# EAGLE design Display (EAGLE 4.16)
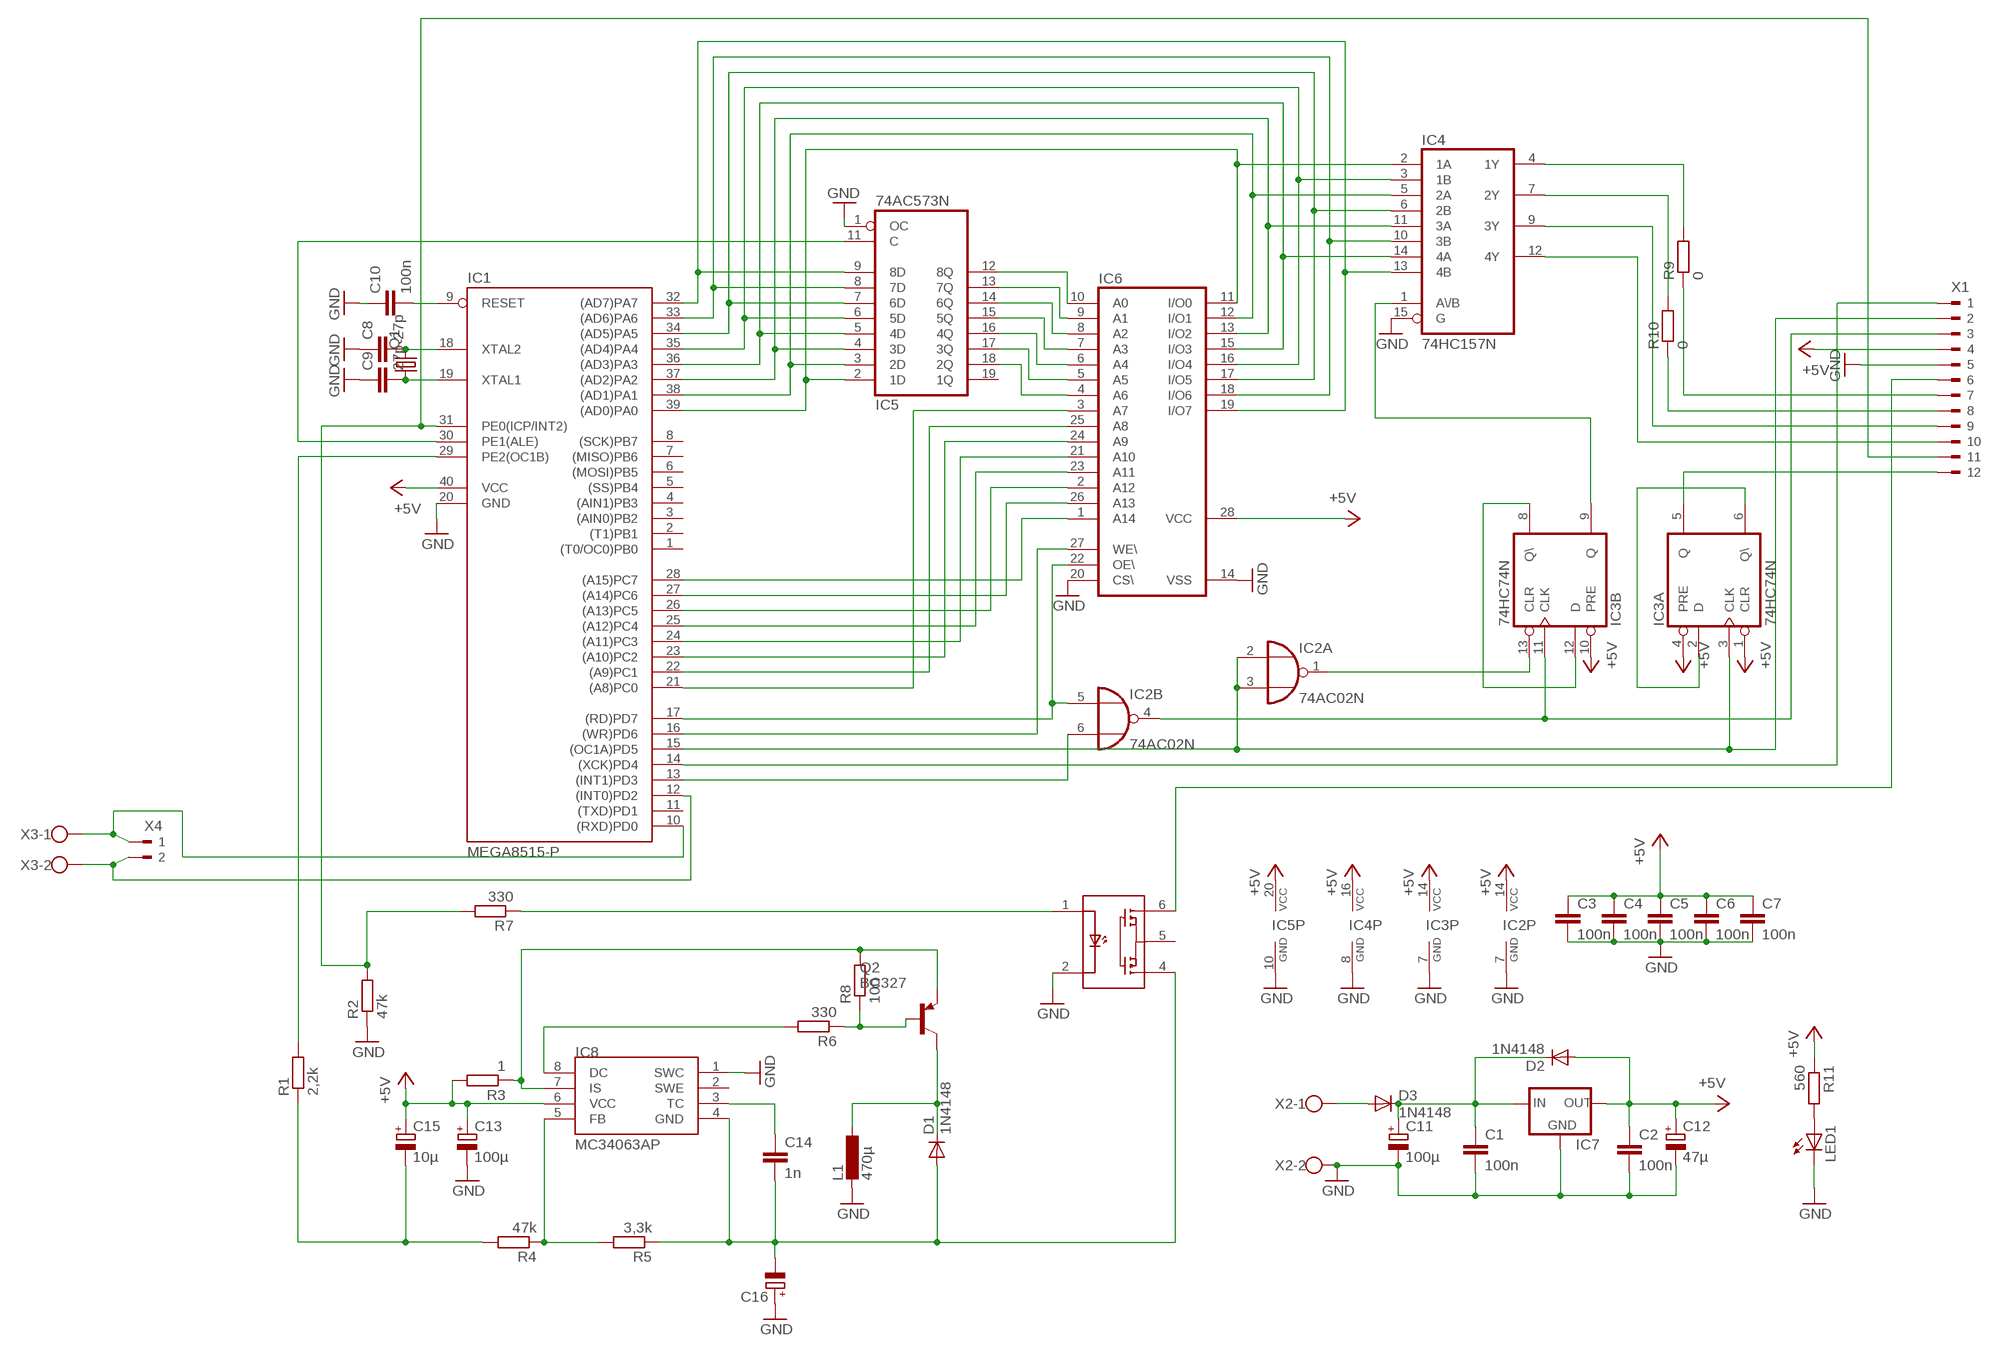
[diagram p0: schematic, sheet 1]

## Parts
C1  100n  C-EUC1206  [C1206]
C2  100n  C-EUC1206  [C1206]
C3  100n  C-EUC1206  [C1206]
C4  100n  C-EUC1206  [C1206]
C5  100n  C-EUC1206  [C1206]
C6  100n  C-EUC1206  [C1206]
C7  100n  C-EUC1206  [C1206]
C8  27p  C-EUC1206  [C1206]
C9  27p  C-EUC1206  [C1206]
C10  100n  C-EUC1206  [C1206]
C11  100µ  CPOL-EUE5-5  [E5-5]
C12  47µ  CPOL-EUE5-5  [E5-5]
C13  100µ  CPOL-EUE5-5  [E5-5]
C14  1n  C-EUC1206  [C1206]
C15  10µ  CPOL-EUE5-5  [E5-5]
C16  CPOL-EUE5-5  [E5-5]
D1  1N4148  [DO35-10]
D2  1N4148  [DO35-10]
D3  1N4148  [DO35-10]
IC1  MEGA8515-P  [DIL40]
IC2  74AC02N  [DIL14]
IC3  74HC74N  [DIL14]
IC4  74HC157N  [DIL16]
IC5  74AC573N  [DIL20]
IC6  62256P  [DIL28-6]
IC7  78XXS  [78XXS]
IC8  MC34063AP  [DIL08]
L1  470µ  L-EU0204/7  [0204/7]
LED1  LEDCHIPLED_1206  [CHIPLED_1206]
Q1  CRYSTALHC49U-V  [HC49U-V]
Q2  BC327  [TO92]
R1  2,2k  R-EU_M1206  [M1206]
R2  47k  R-EU_M1206  [M1206]
R3  1  R-EU_M1206  [M1206]
R4  47k  R-EU_M1206  [M1206]
R5  3,3k  R-EU_M1206  [M1206]
R6  330  R-EU_M1206  [M1206]
R7  330  R-EU_M1206  [M1206]
R8  100  R-EU_M1206  [M1206]
R9  0  R-EU_0207/10  [0207/10]
R10  0  R-EU_0207/10  [0207/10]
R11  560  R-EU_M1206  [M1206]
U$1  AQV254  [AQV257]
X1  180G-12  [180G-12]
X2  W237-102  [W237-102]
X3  W237-102  [W237-102]
X4  180-2  [180-2]

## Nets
+5V: C2.1 C3.1 C4.1 C5.1 C6.1 C7.1 C12.+ C13.+ C15.+ D2.A IC1.40(VCC) IC2.14(P:VCC) IC3.1(A:CLR) IC3.4(A:PRE) IC3.10(B:PRE) IC3.14(P:VCC) IC4.16(VCC) IC5.20(VCC) IC6.28(VCC) IC7.OUT IC8.6(VCC) R3.2 R11.1 X1.4
GND: C1.2 C2.2 C3.2 C4.2 C5.2 C6.2 C7.2 C8.1 C9.1 C10.1 C11.- C12.- C13.- C16.+ IC1.20(GND) IC2.7(P:GND) IC3.7(P:GND) IC4.8(GND) IC4.15(G) IC5.1(OC) IC5.10(GND) IC6.14(VSS) IC6.20(CS\) IC7.GND IC8.1(SWC) L1.2 LED1.C R2.1 U$1.2 X1.5 X2.2
N$1: IC1.39((AD0)PA0) IC4.2(1A) IC5.2(1D) IC6.11(I/O0)
N$2: IC1.38((AD1)PA1) IC4.5(2A) IC5.3(2D) IC6.12(I/O1)
N$3: IC1.37((AD2)PA2) IC4.11(3A) IC5.4(3D) IC6.13(I/O2)
N$4: IC1.36((AD3)PA3) IC4.14(4A) IC5.5(4D) IC6.15(I/O3)
N$5: IC1.35((AD4)PA4) IC4.3(1B) IC5.6(5D) IC6.16(I/O4)
N$6: IC1.34((AD5)PA5) IC4.6(2B) IC5.7(6D) IC6.17(I/O5)
N$7: IC1.33((AD6)PA6) IC4.10(3B) IC5.8(7D) IC6.18(I/O6)
N$8: IC1.32((AD7)PA7) IC4.13(4B) IC5.9(8D) IC6.19(I/O7)
N$9: IC5.12(8Q) IC6.10(A0)
N$10: IC5.13(7Q) IC6.9(A1)
N$11: IC5.14(6Q) IC6.8(A2)
N$12: IC5.15(5Q) IC6.7(A3)
N$13: IC5.16(4Q) IC6.6(A4)
N$14: IC5.17(3Q) IC6.5(A5)
N$15: IC5.18(2Q) IC6.4(A6)
N$16: IC1.21((A8)PC0) IC6.3(A7)
N$17: IC1.22((A9)PC1) IC6.25(A8)
N$18: IC1.23((A10)PC2) IC6.24(A9)
N$19: IC1.24((A11)PC3) IC6.21(A10)
N$20: IC1.25((A12)PC4) IC6.23(A11)
N$21: IC1.26((A13)PC5) IC6.2(A12)
N$22: IC1.27((A14)PC6) IC6.26(A13)
N$23: IC1.28((A15)PC7) IC6.1(A14)
N$24: IC1.16((WR)PD6) IC6.27(WE\)
N$25: IC1.17((RD)PD7) IC2.5(B:I0) IC6.22(OE\)
N$26: IC3.8(B:Q\) IC3.12(B:D)
N$27: IC3.9(B:Q) IC4.1(A\/B)
N$28: IC3.2(A:D) IC3.6(A:Q\)
N$29: IC2.1(A:O) IC3.13(B:CLR)
N$30: IC1.10((RXD)PD0) X3.1 X4.1
N$31: IC1.13((INT1)PD3) IC2.6(B:I1)
N$32: C8.2 IC1.18(XTAL2) Q1.2
N$33: C9.2 IC1.19(XTAL1) Q1.1
N$34: C10.2 IC1.9(RESET)
N$35: IC1.31(PE0(ICP/INT2)) R2.2 R7.2 X1.11
N$36: IC1.15((OC1A)PD5) IC2.2(A:I0) IC2.3(A:I1) IC3.3(A:CLK) X1.2
N$37: IC1.30(PE1(ALE)) IC5.11(C)
N$38: IC3.5(A:Q) X1.12
N$39: IC2.4(B:O) IC3.11(B:CLK) X1.3
N$40: R9.1 X1.7
N$41: R10.1 X1.8
N$42: IC4.9(3Y) X1.9
N$43: IC4.12(4Y) X1.10
N$44: IC1.12((INT0)PD2) X3.2 X4.2
N$45: C14.1 IC8.3(TC)
N$46: C14.2 C16.- D1.A IC8.4(GND) R5.1 U$1.4
N$47: C1.1 C11.+ D2.C D3.C IC7.IN
N$48: IC8.5(FB) R4.1 R5.2
N$49: R7.1 U$1.1
N$50: LED1.A R11.2
N$51: C15.- R1.1 R4.2
N$52: IC1.29(PE2(OC1B)) R1.2
N$53: IC8.8(DC) R6.2
N$54: Q2.2(B) R6.1 R8.1
N$55: IC8.7(IS) Q2.1(E) R3.1 R8.2
N$56: D1.C L1.1 Q2.3(C)
N$57: U$1.6 X1.6
N$58: IC4.4(1Y) R9.2
N$59: IC4.7(2Y) R10.2
N$60: D3.A X2.1
N$61: IC1.14((XCK)PD4) X1.1
Unconnected: IC1.1((T0/OC0)PB0) IC1.2((T1)PB1) IC1.3((AIN0)PB2) IC1.4((AIN1)PB3) IC1.5((SS)PB4) IC1.6((MOSI)PB5) IC1.7((MISO)PB6) IC1.8((SCK)PB7) IC1.11((TXD)PD1) IC2.8(C:I0) IC2.9(C:I1) IC2.10(C:O) IC2.11(D:I0) IC2.12(D:I1) IC2.13(D:O) IC5.19(1Q) IC8.2(SWE) U$1.5

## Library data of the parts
C1-C10 C14 = rcl:C-EU: CAPACITOR, European symbol
C11-C13 C15 C16 = rcl:CPOL-EU: POLARIZED CAPACITOR, European symbol
D1-D3 = diode:1N4148: DIODE
IC1 = atmel:MEGA8515-P: MICROCONTROLLER 8 Kbytes FLASH 512 bytes SRAM 512 bytes EEPROM USART 8-channel 10 bit ADC Source: avr.lbr
IC2 = 74xx-eu:74*02: Quad 2-input NOR gate
IC3 = 74xx-eu:74*74: Dual D type positive edge triggered FLIP FLOP, preset and clear
IC4 = 74xx-eu:74*157: Quadruple 2-line to 1-line data SELECTOR/MULTIPLEXER
IC5 = 74xx-eu:74*573: 8-bit D latch BUS DRIVER
IC6 = memory-hitachi:62256P: MEMORY
IC7 = v-reg:78XXS: VOLTAGE REGULATOR
IC8 = mc34063:MC34063
L1 = rcl:L-EU: INDUCTOR, European symbol
LED1 = led:LED: LED
Q1 = crystal:CRYSTAL: CRYSTAL
Q2 = transistor-pnp:BC327: PNP Transistor
R1-R11 = rcl:R-EU_: RESISTOR, European symbol
U$1 = Relais-Opto:AQV254
X1 = con-weidmueller-sl35:180G-12: WEIDMUELLER CLAMP CONNECTOR
X2 X3 = con-wago-500:W237-102: WAGO SCREW CLAMP
X4 = con-weidmueller-sl35:180-2: WEIDMUELLER CLAMP CONNECTOR

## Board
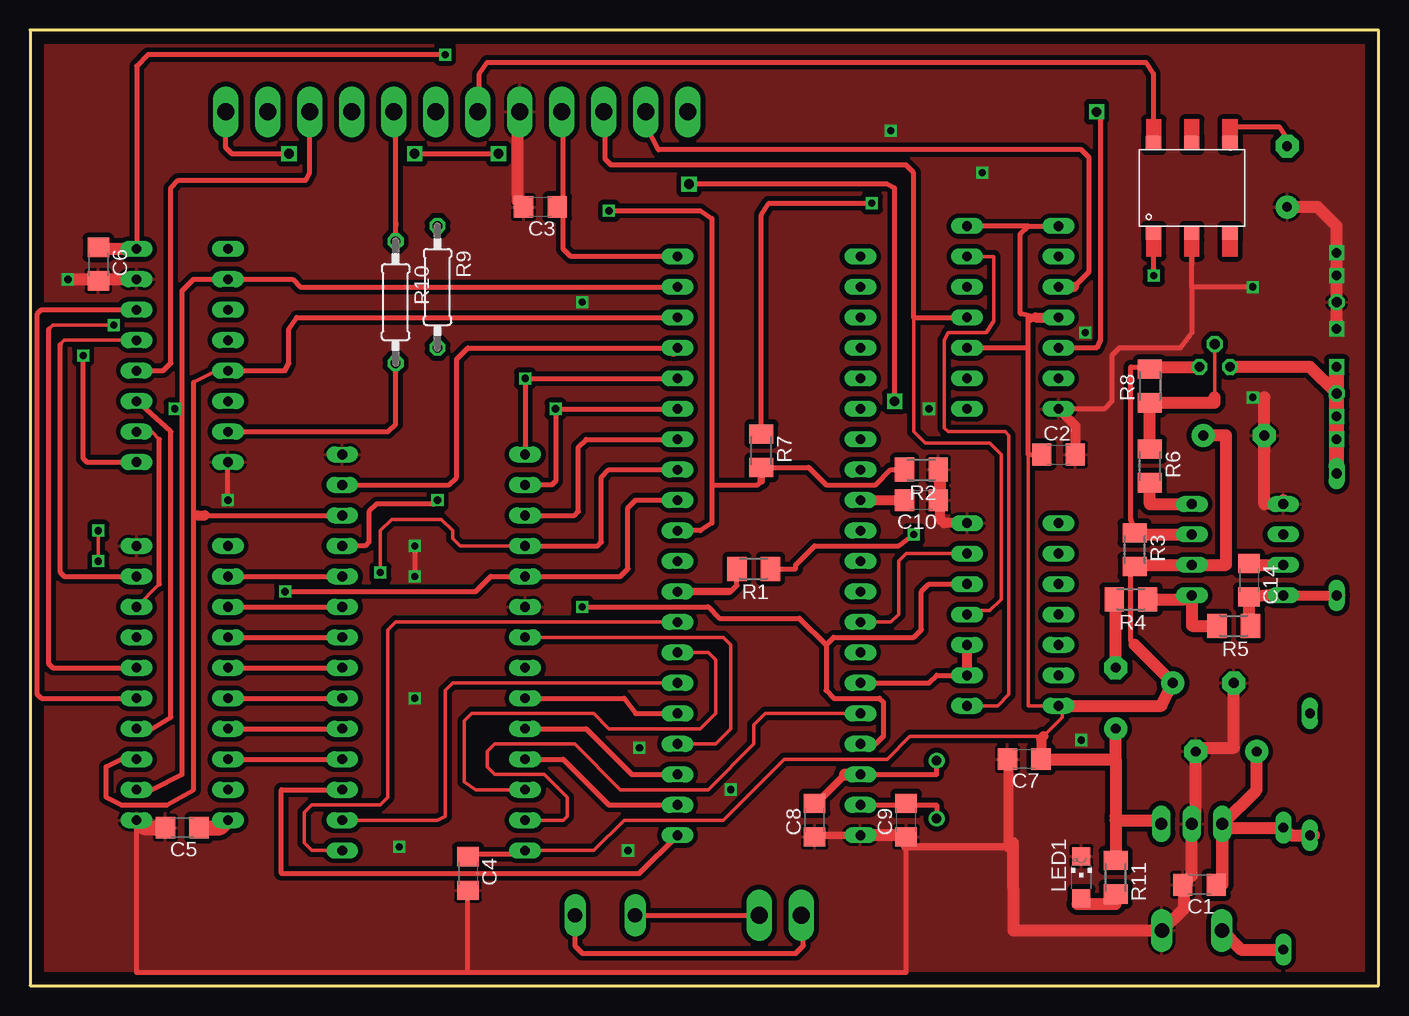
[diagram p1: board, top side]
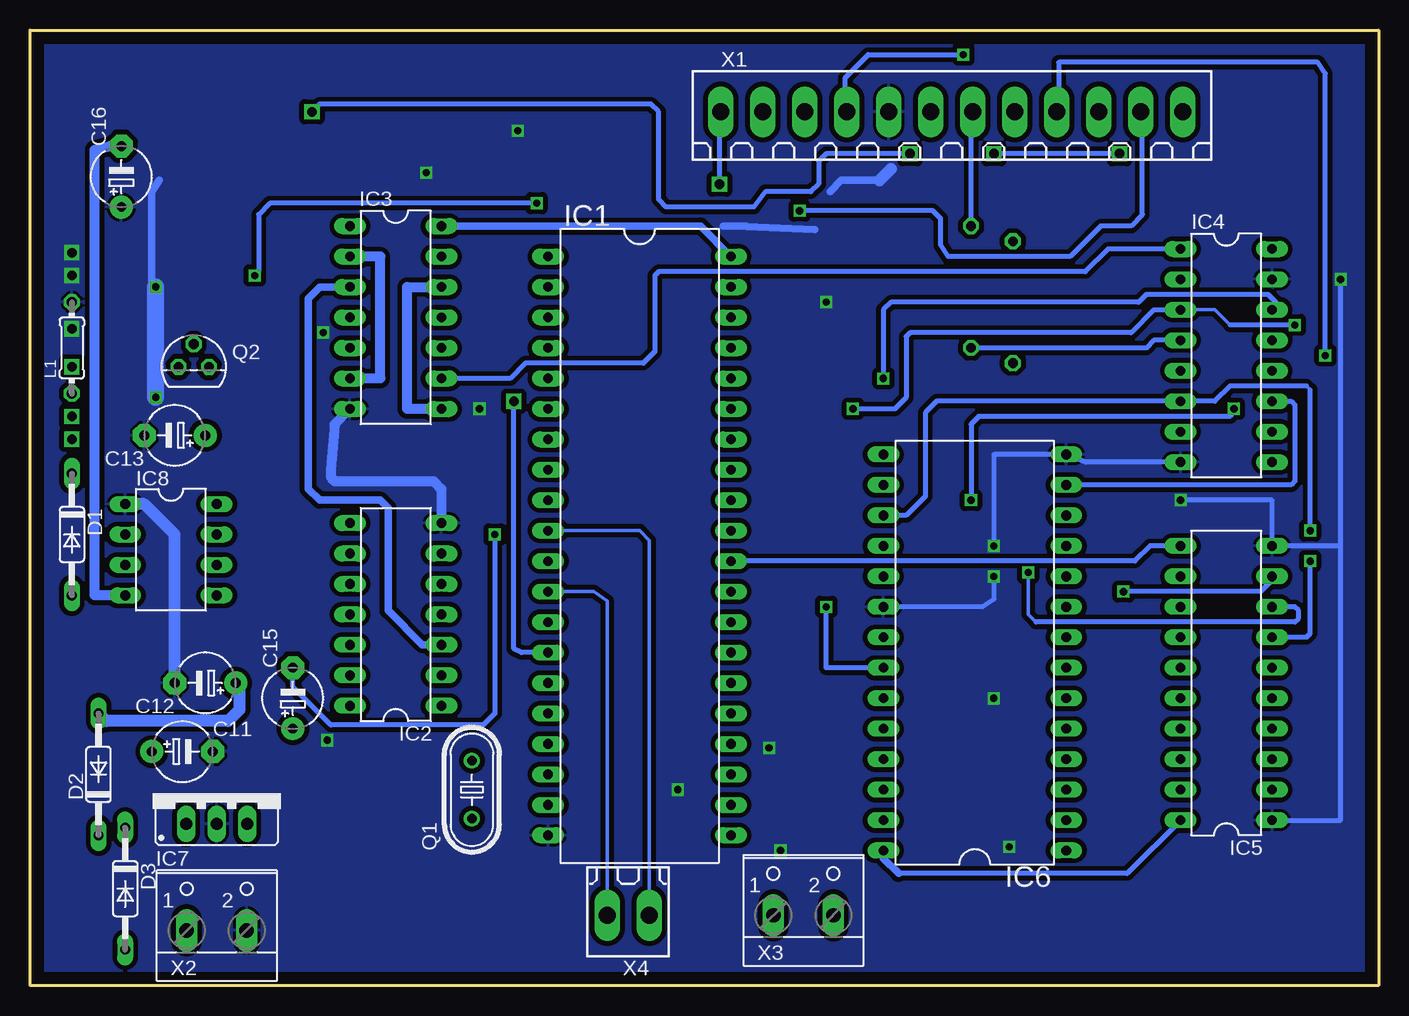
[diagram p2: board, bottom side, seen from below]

Size 112.38 x 79.68 mm. Coordinates in mm from the lower left corner, seen from the top.
Outline: 112.38,79.68 0,79.68 0,0 112.38,0 112.38,79.68
Copper layers (1*16): Top 0.035mm / dielectric 1.5mm / Bottom 0.035mm
Design rules "default": minimum track width 10mil, minimum drill 24mil, track to track 8mil, track to pad 8mil, pad to pad 8mil, via to via 8mil, smd to smd 8mil, copper to edge 40mil, drill to drill 8mil, minimum pad ring 10mil, minimum via ring 8mil, stop-mask expansion 4mil, vias tented up to drill 0mil, thermal gap 10mil

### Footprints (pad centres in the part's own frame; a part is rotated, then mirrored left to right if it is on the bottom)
C1206 = smd 1.6 x 1.8: 1 -1.4,0; 2 1.4,0
E5-5 = drill 0.813 pad 1.905 round: + -2.54,0 | drill 0.813 pad 1.905 octagon: - 2.54,0
DO35-10 = drill 0.813 long: A 5.08,0; C -5.08,0
DIL40 = drill 0.813 long: 1 -24.13,-7.62; 2 -21.59,-7.62; 3 -19.05,-7.62; 4 -16.51,-7.62; 5 -13.97,-7.62; 6 -11.43,-7.62; 7 -8.89,-7.62; 8 -6.35,-7.62; 9 -3.81,-7.62; 10 -1.27,-7.62; 11 1.27,-7.62; 12 3.81,-7.62; 13 6.35,-7.62; 14 8.89,-7.62; 15 11.43,-7.62; 16 13.97,-7.62; 17 16.51,-7.62; 18 19.05,-7.62; 19 21.59,-7.62; 20 24.13,-7.62; 21 24.13,7.62; 22 21.59,7.62; 23 19.05,7.62; 24 16.51,7.62; 25 13.97,7.62; 26 11.43,7.62; 27 8.89,7.62; 28 6.35,7.62; 29 3.81,7.62; 30 1.27,7.62; 31 -1.27,7.62; 32 -3.81,7.62; 33 -6.35,7.62; 34 -8.89,7.62; 35 -11.43,7.62; 36 -13.97,7.62; 37 -16.51,7.62; 38 -19.05,7.62; 39 -21.59,7.62; 40 -24.13,7.62
DIL14 = drill 0.813 long: 1 -7.62,-3.81; 2 -5.08,-3.81; 3 -2.54,-3.81; 4 0,-3.81; 5 2.54,-3.81; 6 5.08,-3.81; 7 7.62,-3.81; 8 7.62,3.81; 9 5.08,3.81; 10 2.54,3.81; 11 0,3.81; 12 -2.54,3.81; 13 -5.08,3.81; 14 -7.62,3.81
DIL16 = drill 0.813 long: 1 -8.89,-3.81; 2 -6.35,-3.81; 3 -3.81,-3.81; 4 -1.27,-3.81; 5 1.27,-3.81; 6 3.81,-3.81; 7 6.35,-3.81; 8 8.89,-3.81; 9 8.89,3.81; 10 6.35,3.81; 11 3.81,3.81; 12 1.27,3.81; 13 -1.27,3.81; 14 -3.81,3.81; 15 -6.35,3.81; 16 -8.89,3.81
DIL20 = drill 0.813 long: 1 -11.43,-3.81; 2 -8.89,-3.81; 3 -6.35,-3.81; 4 -3.81,-3.81; 5 -1.27,-3.81; 6 1.27,-3.81; 7 3.81,-3.81; 8 6.35,-3.81; 9 8.89,-3.81; 10 11.43,-3.81; 11 11.43,3.81; 12 8.89,3.81; 13 6.35,3.81; 14 3.81,3.81; 15 1.27,3.81; 16 -1.27,3.81; 17 -3.81,3.81; 18 -6.35,3.81; 19 -8.89,3.81; 20 -11.43,3.81
DIL28-6 = drill 0.813 long: 1 -16.51,-7.62; 2 -13.97,-7.62; 3 -11.43,-7.62; 4 -8.89,-7.62; 5 -6.35,-7.62; 6 -3.81,-7.62; 7 -1.27,-7.62; 8 1.27,-7.62; 9 3.81,-7.62; 10 6.35,-7.62; 11 8.89,-7.62; 12 11.43,-7.62; 13 13.97,-7.62; 14 16.51,-7.62; 15 16.51,7.62; 16 13.97,7.62; 17 11.43,7.62; 18 8.89,7.62; 19 6.35,7.62; 20 3.81,7.62; 21 1.27,7.62; 22 -1.27,7.62; 23 -3.81,7.62; 24 -6.35,7.62; 25 -8.89,7.62; 26 -11.43,7.62; 27 -13.97,7.62; 28 -16.51,7.62
78XXS = drill 1.016 long: GND 0,-2.54; IN -2.54,-2.54; OUT 2.54,-2.54
DIL08 = drill 0.813 long: 1 -3.81,-3.81; 2 -1.27,-3.81; 3 1.27,-3.81; 4 3.81,-3.81; 5 3.81,3.81; 6 1.27,3.81; 7 -1.27,3.81; 8 -3.81,3.81
0204/7 = drill 0.813 octagon: 1 -3.81,0; 2 3.81,0
CHIPLED_1206 = smd 1.5 x 1.5: A 0,-1.75; C 0,1.75
HC49U-V = drill 0.813 round: 1 -2.413,0; 2 2.413,0
TO92 = drill 0.813 octagon: 1 1.27,0; 2 0,1.905; 3 -1.27,0
M1206 = smd 1.6 x 2: 1 -1.4,0; 2 1.4,0
0207/10 = drill 0.813 octagon: 1 -5.08,0; 2 5.08,0
AQV257 = smd 1.27 x 0.635: 1 -3.2,-3.6; 2 0,-3.6; 3 3.2,-3.6; 4 3.2,3.6; 5 0,3.6; 6 -3.2,3.6; P$7 -3.2,-4; P$8 0,-4; P$9 3.2,-4; P$10 -3.2,4; P$11 0,4; P$12 3.2,4
180G-12 = drill 1.422 long: 1 -19.25,0; 2 -15.75,0; 3 -12.25,0; 4 -8.75,0; 5 -5.25,0; 6 -1.75,0; 7 1.75,0; 8 5.25,0; 9 8.75,0; 10 12.25,0; 11 15.75,0; 12 19.25,0
W237-102 = drill 1.194 long: 1 -2.5,-1.27; 2 2.5,-1.27
180-2 = drill 1.422 long: 1 -1.75,0; 2 1.75,0

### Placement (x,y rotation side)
C1  97.46,8.41 180 top
C2  85.71,44.29 0 top
C3  42.53,64.92 180 top
C4  36.5,9.36 270 top
C5  12.68,13.17 180 top
C6  5.7,60.16 270 top
C7  82.85,18.89 180 top
C8  65.39,13.81 90 top
C9  73.01,13.81 90 top
C10  74.28,40.48 180 top
C11  99.68,19.52 0 bottom
C12  97.78,25.23 180 bottom
C13  100.31,45.87 180 bottom
C14  101.58,33.81 270 top
C15  90.47,23.96 90 bottom
C16  104.76,67.46 90 bottom
D1  108.89,37.62 270 bottom
D2  106.67,17.62 90 bottom
D3  104.44,8.09 270 bottom
IC1  61.58,36.66 270 bottom
IC2  81.9,30.95 90 bottom
IC3  81.9,55.72 270 bottom
IC4  12.68,52.54 270 bottom
IC5  12.68,25.23 90 bottom
IC6  33.64,27.78 90 bottom
IC7  96.82,16.03 0 bottom
IC8  100.63,36.35 270 bottom
L1  108.89,53.18 90 bottom
LED1  87.61,9.04 0 top
Q1  75.55,16.35 90 bottom
Q2  98.73,51.59 0 bottom
R1  60.31,34.76 180 top
R2  74.28,43.02 180 top
R3  92.06,36.35 270 top
R4  91.74,32.22 180 top
R5  100.31,30 180 top
R6  93.33,43.33 270 top
R7  60.95,44.6 270 top
R8  93.33,50 90 top
R9  33.96,58.26 270 top
R10  30.46,56.98 270 top
R11  90.47,9.04 270 top
U$1  96.82,66.51 0 top
X1  35.55,72.86 0 bottom
X2  96.82,5.87 0 bottom
X3  47.93,7.14 0 bottom
X4  62.53,5.87 180 bottom

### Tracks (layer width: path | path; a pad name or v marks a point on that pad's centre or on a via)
+5V  (via drill 0.6)
  Top 0.305: IC6.28 46.98,11.27 49.52,13.81 57.77,13.81 62.85,18.89 71.42,18.89 73.33,20.79 84.44,20.79 86.03,22.38 86.03,23.33 IC2.14 83.17,23.33 83.17,44.29
  Top 0.406: 83.17,55.4 83.8,55.72 83.21,55.86 | 83.17,53.18 IC3.10 | 83.17,63.34 IC3.1 | 83.17,63.34 IC3.14 | 83.21,55.86 82.53,56.03 82.53,62.7 83.17,63.34 | IC1.40 45.07,60.8 44.44,61.43 44.44,64.6 | 44.44,64.6 44.44,72.86 | C3.1 44.12,64.92 44.44,64.6 | R3.2 91.87,34.76 91.74,34.76 91.74,28.73 92.06,28.41 | C2.1 83.17,44.29 83.17,53.18 | 36.31,10.95 36.18,10.95 | 36.31,10.95 C4.1 | IC6.28 40.94,10.95 36.31,10.95 | IC4.16 8.88,76.67 9.83,77.62 v34.59,77.62 | 83.21,55.86 83.21,55.75 83.17,55.72 83.17,55.4 | 83.17,53.18 83.17,55.4
  Top 0.813: 83.8,55.72 IC3.4 | 44.44,73.18 44.44,72.86 X1.4 | C7.1 84.25,20.6 84.44,20.79
  Top 1.016: 5.57,61.43 5.38,61.43 | 5.57,61.43 C6.1 | IC4.16 5.57,61.43 | 86.03,23.33 94.28,23.33 C12.+ 92.06,28.41 | R3.2 91.87,34.95 91.74,35.08 IC8.6 99.68,35.08 99.68,45.87 C13.+ | 90.47,18.89 90.47,14.12 | 90.47,14.12 90.47,13.81 93.97,13.81 IC7.OUT | 90.47,18.89 C15.+ | C7.1 90.47,18.89 | 90.47,14.12 R11.1
  Top 1.27: IC5.20 15.86,13.17 C5.1
  Bottom 0.406: IC5.20 20.94,9.36 39.99,9.36 | v34.59,77.62 42.53,77.62 44.44,75.72 44.44,72.86 X1.4
  Bottom 0.61: 39.99,9.36 41.26,10.63 IC6.28 | IC1.40 56.5,63.34 IC3.14
  Bottom 1.016: D2.A 106.03,22.06 95.87,22.06 94.92,23.01 94.92,25.23 C12.+
GND  (via drill 0.6, 0.6 pad 0.81, 0.8 pad 1.27)
  Top 0.406: IC5.1 8.88,1.1 36.5,1.1 | 36.5,1.1 73.01,1.1 C9.1 | 96.82,60.8 96.82,60.16 | 96.82,60.8 U$1.2 | IC3.7 89.52,48.09 90.16,48.73 90.16,52.54 90.79,53.18 95.87,53.18 96.82,54.45 96.82,58.26 | 36.5,1.1 C4.2 | 96.82,58.26 96.82,60.8 | v101.9,58.26 96.82,58.26 | v3.16,58.89 3.79,58.89 | v16.5,40.48 IC4.8 | v32.05,36.66 v32.05,34.12
  Top 0.61: IC1.20 65.39,12.54 | 73.01,11.58 81.58,11.58
  Top 0.813: IC2.7 76.19,38.57 75.87,38.89 75.87,40.48 C10.1 | C2.2 87.11,46.7 IC3.7 | 73.01,12.54 73.01,11.58 | C7.2 81.58,18.89 81.58,11.58 | 102.86,49.05 v101.9,49.05
  Top 1.016: 5.7,58.89 IC4.15 | C9.1 73.01,12.54 IC1.20 | 65.39,12.54 C8.1 | 5.7,58.89 C6.2 | 3.79,58.89 5.7,58.89 | R2.1 75.87,43.02 75.87,40.66 C10.1 | 81.9,11.58 81.94,4.6 X2.2 96.19,6.46 96.19,8.41 C1.2 96.82,9.17 IC7.GND 97.14,13.81 C11.- 97.14,19.84 100.31,19.84 C12.- 100.31,25.55 | 81.9,11.58 81.9,11.9 | C13.- 102.86,40.16 IC8.1 104.44,40.48 | C13.- 102.86,44.6 | C13.- 102.86,49.05 | 81.58,11.58 81.9,11.58 | C16.+ 107.3,64.92 108.89,63.34 v108.89,61.11 v108.89,59.21 L1.2 v108.89,54.76 | X1.5 40.62,72.86 40.62,65.43 C3.2
  Top 1.27: IC5.1 9.51,13.17 C5.2
  Bottom 0.406: IC4.8 24.43,43.65 IC6.14 32.05,44.29 v32.05,36.66 | 3.16,36.66 IC5.10 8.88,40.48 v16.5,40.48 | 3.16,36.66 3.16,13.81 IC5.1 | 3.16,36.66 v3.16,58.89 | v32.05,34.12 32.05,32.22 33.01,31.59 IC6.20 | 41.58,67.14 40.94,67.78 | v101.9,58.26 102.22,58.26
  Bottom 0.61: 101.58,67.14 102.22,66.19 102.22,58.26 | 53.64,63.34 54.59,63.34 | 53.64,63.34 52.69,63.34 | 46.98,63.02 53.64,63.34 | 45.7,66.19 44.75,67.14 41.58,67.14
  Bottom 0.813: IC2.7 78.09,41.43 78.72,42.06 86.98,42.06 87.3,42.38 87.3,43.02 86.98,46.83 IC3.7
  Bottom 1.016: C12.- 100.31,37.62 102.86,40.16 IC8.1 | X1.5 40.62,72.86 | 40.62,68.1 41.58,67.14
  Bottom 1.422: v101.9,49.05 v101.9,58.26
  other vias: 32.05,23.96 30.78,11.58 50.78,19.84 49.83,11.27 58.41,16.35 71.74,71.27 46.02,56.98 74.92,48.09 87.93,54.45 87.61,20.47 79.36,67.78
  pour Bottom (isolate 0.406): -0.01,79.53 -0.01,-0.17 112.38,-0.17 112.38,79.53
  pour Top (isolate 0.406): -0.01,79.84 -0.01,0.15 112.38,0.15 112.38,79.53 -0.01,79.53
N$1  (via drill 0.6)
  Top 0.305: 13.64,58.89 IC4.2
  Top 0.406: IC5.2 10.14,16.35 12.68,17.62 12.68,48.41 | IC1.39 22.53,58.26 21.89,58.89 | IC4.2 21.89,58.89 | 21.89,58.89 13.64,58.89 12.68,57.94 12.68,48.41 | 12.68,48.41 12.37,48.09 v12.05,48.09 | v33.96,40.48 33.64,40.16 28.88,40.16 28.24,39.52 28.24,36.98 27.93,36.66 IC6.11
  Bottom 0.406: v12.05,48.09 12.37,47.46 33.32,47.46 33.96,46.83 v33.96,40.48
N$2
  Top 0.305: 13.64,50.32 15.54,51.27 IC4.5 | 16.81,51.27 16.81,51.59
  Top 0.406: IC5.3 7.61,18.89 6.33,18.25 6.33,15.71 7.61,15.08 11.41,15.08 13.64,16.35 13.64,39.2 | 13.64,39.2 13.64,50.32 | IC6.12 13.96,39.2 13.64,39.2 | IC1.38 22.21,55.72 21.57,54.76 21.57,51.91 21.26,51.27 16.81,51.27
  Top 0.813: 13.96,39.2 14.59,39.2 | IC4.5 16.81,51.27
N$3
  Top 0.305: IC5.4 10.14,21.43
  Top 0.406: 10.14,21.43 11.73,22.38 11.73,46.19 IC4.11 | IC6.13 34.91,41.74 35.55,42.38 35.55,52.22 36.5,53.18 53.64,53.18
  Top 0.813: IC1.37 53.64,53.18 53.64,52.86
  Bottom 0.406: IC6.13 7.29,41.74 6.97,42.06 6.97,48.41 7.29,48.73 IC4.11
N$4  (via drill 0.6)
  Top 0.406: IC1.36 v41.26,50.63 IC6.15 | IC4.14 0.94,56.35 0.62,56.03 0.62,24.28 0.94,23.96 IC5.5
  Bottom 0.406: v41.26,50.63 41.26,56.35 40.62,56.98 19.99,56.98 19.35,57.62 9.19,57.62 8.56,56.98 8.56,56.67 IC4.14
N$5  (via drill 0.6)
  Top 0.305: v6.97,55.08 1.89,55.08 1.57,54.76
  Top 0.406: IC6.16 43.48,41.74 43.8,42.06 v43.8,48.09 IC1.35 | 1.57,54.76 1.57,26.82 1.89,26.51 IC5.6
  Bottom 0.305: 18.72,56.35 13.64,56.35 12.37,55.08
  Bottom 0.406: v43.8,48.09 40.31,48.09 39.35,49.05 39.35,54.13 39.04,54.45 20.62,54.45 18.72,56.35 IC4.3 | v6.97,55.08 12.37,55.08
N$6  (via drill 0.6)
  Top 0.305: v5.7,35.4 v5.7,37.94
  Top 0.406: IC6.17 45.39,39.2 45.7,39.52 45.7,44.92 46.34,45.55 IC1.34
  Bottom 0.305: 5.7,49.68 6.02,50 | IC5.7 9.19,29.05
  Bottom 0.406: IC6.17 39.35,39.2 37.77,40.79 37.77,47.78 36.81,48.73 IC4.6 13.64,48.73 12.37,50 6.02,50 | v5.7,37.94 5.7,49.68 | v5.7,35.4 5.7,29.36 6.02,29.05 IC5.7
N$7  (via drill 0.6)
  Top 0.305: 10.78,45.55 10.14,46.19 IC4.10 | IC5.8 10.78,33.49 | v29.2,34.44 29.2,37.94 30.15,38.89 34.27,38.89 35.23,37.94 35.23,37.3 35.86,36.66 41.58,36.66
  Top 0.406: IC6.18 41.58,36.66 47.29,36.66 47.61,36.98 47.61,42.38 48.24,43.02 IC1.33 | 10.78,33.49 10.78,45.55
  Bottom 0.305: 28.56,30.32 29.2,30.95 v29.2,34.44
  Bottom 0.406: IC5.8 6.97,31.59 6.65,31.27 6.65,30.63 6.97,30.32 28.56,30.32
  other vias: 8.88,31.59
N$8  (via drill 0.6)
  Top 0.305: 2.52,53.49 2.84,53.81 IC4.13
  Top 0.406: IC1.32 50.47,40.48 49.83,39.84 49.83,34.76 49.2,34.12 IC6.19 38.4,34.12 37.13,32.86 v21.26,32.86 | 2.52,53.49 2.52,34.44 2.84,34.12 IC5.9
  Bottom 0.406: v21.26,32.86 9.83,32.86 8.88,33.81 IC5.9
N$9
  Top 0.406: IC5.12 IC6.10
N$10
  Top 0.406: IC5.13 IC6.9
N$11
  Top 0.406: IC5.14 IC6.8
N$12
  Top 0.406: IC5.15 IC6.7
N$13
  Top 0.406: IC5.16 IC6.6
N$14
  Top 0.406: IC5.17 IC6.5
N$15
  Top 0.406: IC5.18 IC6.4
  Top 1.016: IC5.18 15.86,18.89
N$16
  Top 0.406: IC1.21 50.78,9.36 20.94,9.36 20.94,16.35 IC6.3
N$17
  Top 0.406: IC1.22 48.24,15.08 44.44,18.89 IC6.25
N$18
  Top 0.406: IC1.23 50.15,17.62 46.34,21.43 IC6.24
N$19
  Top 0.305: IC1.24 57.13,20.16 58.41,21.43 58.41,28.41 57.77,29.05 IC6.21
N$20
  Top 0.406: IC6.23 49.52,23.96 50.47,22.7 IC1.25
N$21
  Top 0.305: IC6.2 33.96,13.81 34.59,14.12 34.59,24.6 35.23,25.23 IC1.26
N$22
  Top 0.305: IC1.27 56.5,27.78 57.13,27.14 57.13,22.7 55.87,21.43 48.24,21.43 46.98,22.7 36.81,22.7 36.18,22.06 36.18,16.98 37.13,16.35 IC6.26
N$23
  Top 0.305: IC6.1 23.48,11.27 22.84,11.9 22.84,14.44 23.48,15.08 29.2,15.08 29.83,15.71 29.83,29.68 30.46,30.32 IC1.28
N$24
  Top 0.305: IC6.27 44.44,13.81 44.75,14.12 44.75,15.71 42.85,17.62 38.72,17.62 38.09,18.25 38.09,19.52 38.72,20.16 45.39,20.16 49.2,16.35 56.5,16.35 60.31,20.16 60.31,21.74 61.26,22.7 IC1.16
N$25  (via drill 0.6)
  Top 0.406: IC2.5 74.92,33.49 74.28,32.86 74.28,29.68 73.64,29.05 66.98,29.05 66.34,28.41 | 66.34,28.41 66.34,24.6 66.98,23.96 70.79,23.96 71.11,23.65 71.11,20.79 70.47,20.16 IC1.17 68.88,20.16 | 66.34,28.41 64.12,30.63 57.45,30.63 56.5,31.59 v46.02,31.59
  Bottom 0.406: v46.02,31.59 46.02,26.51 IC6.22 40.94,26.51
N$26
  Bottom 0.813: IC3.8 80.95,48.09 80.95,58.26 IC3.12
N$27
  Bottom 0.406: IC3.9 72.38,50.63 71.11,51.91 61.26,51.91 60.31,52.86 60.31,59.21 59.99,59.52 24.43,59.52 22.53,61.43 IC4.1
N$28
  Bottom 0.813: IC3.6 83.17,50.63 83.17,60.8 IC3.2
N$29
  Top 0.305: IC3.13 80.31,60.8 80.31,55.4 79.68,54.45 76.5,54.45 76.19,53.81 76.19,46.51 76.5,46.19 81.27,46.19 81.58,45.87 81.58,24.28 80.63,23.33 IC2.1
N$30
  Top 0.406: X3.1 X4.1
  Top 0.813: X3.1 50.15,5.87
  Bottom 0.305: X4.1 60.78,37.14 61.58,37.94 IC1.10
N$31
  Top 0.305: IC1.13 71.74,30.32 72.38,30.95 72.38,35.4 73.01,36.03 IC2.6
N$32
  Top 0.406: Q1.2 75.55,17.62 IC1.18
  Top 0.61: 65.39,15.08 67.93,17.62
  Top 1.016: C8.2 65.39,15.08 | 67.93,17.62 IC1.18
N$33
  Top 0.406: Q1.1 75.55,15.08 73.01,15.08 IC1.19
  Top 1.016: 73.01,15.08 C9.2
N$34
  Top 0.813: IC1.9 C10.2
N$35  (via drill 0.6)
  Top 0.406: IC1.31 55.87,37.94 56.82,38.57 56.82,41.74 | 56.82,41.74 56.82,63.97 55.87,64.6 v48.24,64.6 | R7.2 64.89,43.2 66.34,41.74 70.47,41.74 71.74,43.02 R2.2 73.01,43.02 | 60.95,42.06 60.63,41.74 56.82,41.74
  Top 0.61: 60.95,42.06 R7.2
  Top 1.016: R7.2 60.95,43.33
  Bottom 0.406: v48.24,64.6 37.13,64.6 36.5,63.97 36.5,61.75 35.86,60.8 25.7,60.8 23.16,63.34 20.62,63.34 19.67,64.29 19.67,72.86 | 19.67,72.86 X1.11 | 19.67,72.86 19.67,73.18
N$36
  Top 0.406: IC1.15 74.92,25.23 75.55,25.87 IC2.2 | 51.3,71.71 52.37,69.68 87.61,69.68 88.25,69.05 88.25,59.52 86.98,58.26
  Top 0.813: IC2.2 IC2.3 | 51.3,71.71 X1.2 | IC3.3 86.98,58.26
  Bottom 0.61: IC2.3 79.68,28.41 82.53,31.27 82.53,39.84 83.17,40.48 88.25,40.48 89.2,41.43 89.2,57.3 88.25,58.26 IC3.3
N$37
  Bottom 0.406: IC1.30 20.3,35.4 19.04,36.66 IC5.11
N$38  (via drill 0.8 pad 1.27)
  Top 0.406: IC3.5 88.89,53.18 89.2,53.81 89.2,72.22 v88.89,72.86 | X1.12 16.29,69.88 16.81,69.37 v21.57,69.37 | v32.05,69.37 v39.04,69.37
  Bottom 0.406: v21.57,69.37 v32.05,69.37 | v39.04,69.37 46.02,69.37 46.66,68.73 46.66,66.83 47.29,66.19 51.1,66.19 52.05,64.92 59.36,64.92 59.99,65.56 59.99,72.86 60.63,73.49 88.25,73.49 v88.89,72.86
N$39
  Top 0.305: 73.64,55.72 73.64,46.19 74.6,45.24 80,45.24 80.95,44.29 80.95,32.22 80,31.27 78.09,31.27 IC2.4
  Top 0.406: IC3.11 73.64,55.72 73.64,67.78 73.01,68.41 48.43,68.41 47.93,68.92 47.93,72.86 X1.3
  Top 0.813: IC3.11 78.72,55.72
N$40
  Bottom 0.406: X1.7 33.96,73.18 R9.1
N$41
  Top 0.406: X1.8 30.46,72.69 30.46,63.65 | 30.46,63.65 30.46,63.34 | R10.1 30.46,63.65
N$42  (via drill 0.6)
  Top 0.406: IC4.9 4.75,43.65 4.43,43.97 v4.43,52.54
  Bottom 0.406: v4.43,52.54 4.43,76.03 5.07,76.99 26.66,76.99 26.66,73.18 X1.9
N$43
  Top 0.406: X1.10 23.29,67.78 22.98,67.14 12.37,67.14 11.73,66.51 11.73,51.91 11.1,51.27 IC4.12
  Top 0.813: IC4.12 8.56,51.27
N$44
  Top 0.406: X3.2 45.43,3.29 46.02,2.69 63.8,2.69 64.44,3.33 64.44,5.71 X4.2
  Bottom 0.305: X4.2 64.28,32.06 65.39,32.86 IC1.12
N$45
  Top 1.016: 101.58,35.4 C14.1 101.58,35.08 IC8.3
N$46
  Top 0.406: C16.- 104.76,70.64 104.12,71.59 100,71.59 100,70.11
  Top 0.813: 109.2,32.54 D1.A IC8.4
  Top 1.016: C14.2 101.58,32.54 | R5.1 101.58,30 C14.2 | C14.2 104.44,32.73 IC8.4 | 100,70.11 U$1.4
  Bottom 0.813: C16.- 105.71,70 106.98,69.68 106.98,32.54 IC8.4 104.12,32.54
N$47
  Top 1.016: C1.1 98.73,8.41 | C1.1 99.32,8.41 99.36,8.45 IC7.IN | IC7.IN 99.36,13.81 | C1.1 99.36,8.91 IC7.IN | IC7.IN 102.22,16.35 C11.+ | IC7.IN 99.68,13.17 D3.C 105.08,12.54 D2.C 106.98,12.54
N$48
  Top 1.016: R4.1 96.19,32.22 IC8.5 96.82,30 R5.2
N$49  (via drill 0.6)
  Top 0.406: R7.1 60.95,64.29 61.58,65.24 v70.15,65.24 | U$1.1 93.62,62.73 93.65,62.7 v93.65,59.21
  Bottom 0.406: v70.15,65.24 92.38,65.24 93.33,64.29 93.33,59.52 v93.65,59.21
N$50
  Top 1.016: R11.2 90.47,6.82 87.3,6.82 87.61,7.14 LED1.A
N$51  (via drill 0.6)
  Top 0.406: R1.1 63.8,34.76 63.8,35.08 65.39,36.66 72.38,36.66 v73.64,37.62
  Top 1.016: R4.2 90.47,32.22 C15.-
  Bottom 0.406: v73.64,37.62 73.64,22.7 74.6,21.74 87.3,21.74 90.47,24.92 C15.-
N$52
  Top 0.406: 58.22,32.86 58.41,32.86 58.91,33.36 R1.2
  Top 0.61: IC1.29 58.22,32.86
N$53
  Top 1.016: 93.33,42.06 R6.2 93.33,40.16 IC8.8
N$54
  Top 0.305: 98.73,49.05 Q2.2
  Top 1.016: R8.1 93.33,48.73 | R6.1 R8.1 | R8.1 98.73,48.6 98.73,49.05
N$55
  Top 0.406: 93.01,51.59 91.74,51.59 91.74,38.89 92.06,37.94 R3.1
  Top 1.016: R8.2 93.01,51.4 93.01,51.59 Q2.1 | R3.1 91.87,37.75 91.74,37.62 IC8.7
N$56  (via drill 0.8 pad 1.27)
  Top 1.016: L1.1 106.67,51.59 Q2.3
  Top 1.27: D1.C v108.89,45.55 v108.89,47.46 L1.1 v108.89,51.59
N$57
  Top 0.406: U$1.6 93.62,76.03 92.99,76.99 38.09,76.99 37.45,76.03 37.45,72.86
  Top 1.016: X1.6 37.45,72.86
N$58
  Bottom 0.406: R9.2 19.35,53.18 18.72,53.81 IC4.4 16.18,53.81
N$59
  Top 0.406: IC4.7 29.83,46.19 30.46,46.83 R10.2
N$60
  Top 1.016: X2.1 100.91,3.01 D3.A
N$61  (via drill 0.8 pad 1.27)
  Top 0.406: v72.06,48.73 72.06,66.51 71.42,66.83 v54.91,66.83
  Bottom 0.406: IC1.14 71.42,27.78 72.06,28.09 v72.06,48.73 | X1.1 54.8,73.06 54.91,73.18 v54.91,66.83
(copper drawn outside any net)
  shapes: Top area x6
